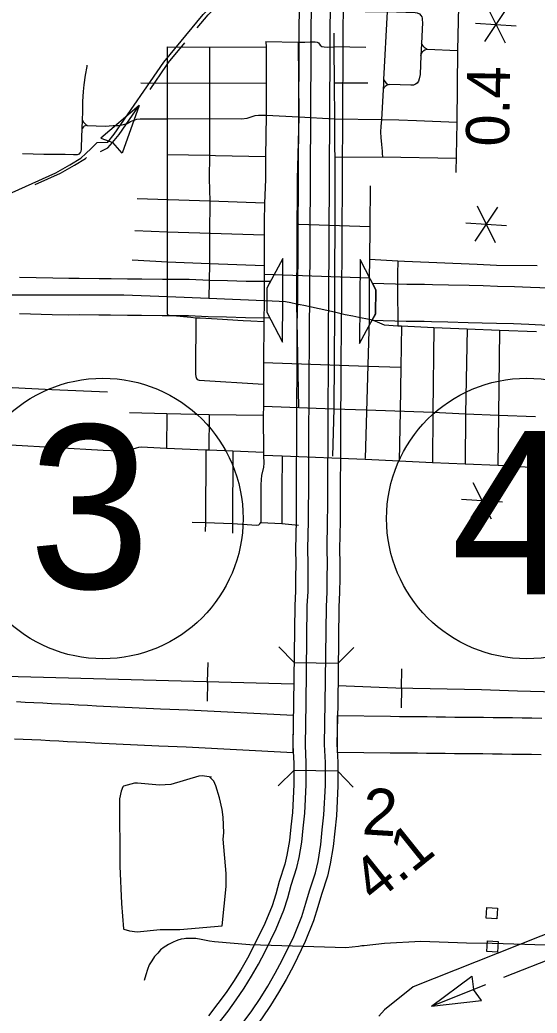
# Model space of a CAD drawing. Extents: x 1366406 to 1373462, y 376856 to 381998.
# Drawn here: x 1369320 to 1369377, y 379865.5 to 379974.8 of the extents above; entities that cross this region are included whole.
import ezdxf

# ---------------------------------------------------------------- set-up
doc = ezdxf.new("R2010")
doc.units = 0
for name, color, linetype in [('10', 7, 'Continuous'), ('19', 7, 'Continuous'), ('33', 7, 'Continuous'), ('35', 7, 'Continuous'), ('39', 7, 'Continuous'), ('40', 7, 'Continuous'), ('42', 7, 'Continuous'), ('43', 7, 'Continuous'), ('48', 7, 'Continuous'), ('56', 7, 'Continuous'), ('R_Draft', 7, 'Continuous')]:
    doc.layers.add(name, color=color, linetype=linetype)

msp = doc.modelspace()

# ---------------------------------------------------------------- linework, layer by layer
at = {"layer": '10'}
for points in [[(1369319.95, 379946.52), (1369323.62, 379946.42), (1369325.37, 379946.39), (1369326.53, 379946.41), (1369328.74, 379946.37), (1369330.03, 379946.36), (1369331.86, 379946.34), (1369333.42, 379946.34), (1369335.7, 379946.29), (1369338.64, 379946.29), (1369340.87, 379946.19), (1369342.86, 379946.15), (1369344.92, 379946.08), (1369347.02, 379946.07), (1369347.62, 379946.06), (1369347.21, 379945.29), (1369347.19, 379942.66), (1369347.53, 379942.01)], [(1369358.84, 379945.81), (1369359.2, 379945.12), (1369359.18, 379942.49), (1369358.78, 379941.76), (1369362.55, 379941.65), (1369364.54, 379941.65), (1369365.35, 379941.63), (1369367.13, 379941.59), (1369369.38, 379941.53), (1369370.91, 379941.49), (1369372.49, 379941.43), (1369374.37, 379941.4), (1369376.08, 379941.32), (1369378.2, 379941.24)], [(1369378.31, 379945.29), (1369376.25, 379945.37), (1369374.49, 379945.44), (1369372.6, 379945.47), (1369371.05, 379945.54), (1369369.49, 379945.58), (1369367.22, 379945.64), (1369365.44, 379945.68), (1369364.59, 379945.7), (1369362.61, 379945.7), (1369358.84, 379945.81)], [(1369347.53, 379942.01), (1369344.83, 379942.03), (1369342.75, 379942.1), (1369340.73, 379942.14), (1369338.55, 379942.24), (1369335.66, 379942.24), (1369333.38, 379942.29), (1369331.84, 379942.28), (1369329.98, 379942.31), (1369328.69, 379942.32), (1369326.52, 379942.36), (1369325.37, 379942.34), (1369323.54, 379942.37), (1369319.94, 379942.47)], [(1369350.11, 379894.18), (1369350.13, 379898.24), (1369338.51, 379898.82), (1369337.5, 379898.87), (1369336.5, 379898.91), (1369335.49, 379898.96), (1369328.44, 379899.29), (1369327.44, 379899.34), (1369326.45, 379899.39), (1369325.46, 379899.45), (1369324.47, 379899.5), (1369323.48, 379899.54), (1369322.5, 379899.59), (1369321.53, 379899.64), (1369320.56, 379899.69), (1369319.6, 379899.74)], [(1369354.98, 379894.18), (1369354.99, 379898.23), (1369360.83, 379898.16), (1369361.82, 379898.15), (1369362.82, 379898.14), (1369363.83, 379898.14), (1369364.85, 379898.13), (1369365.87, 379898.11), (1369366.89, 379898.1), (1369367.92, 379898.08), (1369368.96, 379898.08)], [(1369368.96, 379898.08), (1369370.01, 379898.07), (1369371.06, 379898.06), (1369372.12, 379898.04), (1369373.18, 379898.03), (1369374.25, 379898.01), (1369375.33, 379897.99), (1369376.41, 379897.99), (1369377.5, 379897.97)], [(1369319.41, 379895.69), (1369320.36, 379895.65), (1369321.32, 379895.6), (1369322.29, 379895.55), (1369323.28, 379895.5), (1369324.27, 379895.45), (1369325.25, 379895.4), (1369326.23, 379895.35), (1369327.24, 379895.3), (1369328.25, 379895.25), (1369335.3, 379894.92), (1369336.31, 379894.87), (1369337.32, 379894.82), (1369338.31, 379894.78), (1369350.11, 379894.18)], [(1369368.93, 379894.03), (1369367.89, 379894.04), (1369366.84, 379894.05), (1369365.81, 379894.06), (1369364.8, 379894.08), (1369363.8, 379894.09), (1369362.79, 379894.09), (1369361.78, 379894.1), (1369360.79, 379894.11), (1369354.98, 379894.18)], [(1369377.44, 379893.92), (1369376.37, 379893.94), (1369375.29, 379893.95), (1369374.2, 379893.96), (1369373.12, 379893.98), (1369372.06, 379893.99), (1369371, 379894.01), (1369369.97, 379894.02), (1369368.93, 379894.03)]]:
    msp.add_lwpolyline(points, dxfattribs=at)
at = {"layer": '19'}
for points in [[(1369352.16, 379985.3), (1369350.78, 379985.31), (1369350.56, 379943.93), (1369350.52, 379941.32), (1369350.52, 379939.77), (1369350.51, 379938.23), (1369350.5, 379936.7), (1369350.49, 379935.16), (1369350.48, 379933.63), (1369350.47, 379932.09), (1369350.47, 379930.55), (1369350.46, 379929.01), (1369350.45, 379927.47), (1369350.44, 379925.91), (1369350.43, 379924.35), (1369350.43, 379922.79), (1369350.42, 379921.24), (1369350.42, 379919.72), (1369350.34, 379916.54), (1369350.38, 379914.96), (1369350.37, 379913.44), (1369350.36, 379911.93), (1369350.28, 379910.36), (1369350.15, 379899.59)], [(1369351.53, 379899.58), (1369351.66, 379910.32), (1369351.74, 379911.89), (1369351.75, 379913.43), (1369351.76, 379914.98), (1369351.72, 379916.55), (1369351.79, 379919.7), (1369351.8, 379921.24), (1369351.81, 379922.79), (1369351.81, 379924.34), (1369351.82, 379925.9), (1369351.83, 379927.46), (1369351.84, 379929), (1369351.84, 379930.54), (1369351.85, 379932.08), (1369351.86, 379933.62), (1369351.87, 379935.16), (1369351.88, 379936.69), (1369351.89, 379938.23), (1369351.89, 379939.77), (1369351.9, 379941.31), (1369351.93, 379943.92), (1369352.16, 379985.3)], [(1369353.63, 379899.55), (1369353.76, 379910.25), (1369353.84, 379911.83), (1369353.85, 379913.41), (1369353.87, 379914.99), (1369353.83, 379916.55), (1369353.9, 379919.67), (1369353.91, 379921.23), (1369353.91, 379922.78), (1369353.92, 379924.33), (1369353.92, 379925.89), (1369353.94, 379927.44), (1369353.94, 379928.99), (1369353.95, 379930.53), (1369353.96, 379932.07), (1369353.96, 379933.61), (1369353.98, 379935.14), (1369353.98, 379936.68), (1369353.99, 379938.22), (1369354, 379939.76), (1369354.01, 379941.29), (1369354.04, 379943.9), (1369354.26, 379985.29)], [(1369354.26, 379985.29), (1369355.64, 379985.29), (1369355.42, 379943.88), (1369355.38, 379941.28), (1369355.38, 379939.75), (1369355.37, 379938.21), (1369355.36, 379936.67), (1369355.35, 379935.13), (1369355.34, 379933.6), (1369355.33, 379932.07), (1369355.33, 379930.53), (1369355.32, 379928.98), (1369355.31, 379927.43), (1369355.3, 379925.88), (1369355.29, 379924.33), (1369355.29, 379922.78), (1369355.28, 379921.22), (1369355.28, 379919.65), (1369355.2, 379916.55), (1369355.24, 379915), (1369355.23, 379913.4), (1369355.22, 379911.79), (1369355.14, 379910.21), (1369355.01, 379899.53)], [(1369337.9, 379860.21), (1369338.82, 379861.06), (1369339.98, 379862.15), (1369341.05, 379863.38), (1369341.85, 379864.3), (1369342.92, 379865.7), (1369343.83, 379866.95), (1369344.69, 379868.22), (1369345.51, 379869.53), (1369346.29, 379870.87), (1369347.01, 379872.25), (1369348.24, 379874.77), (1369349.07, 379876.83), (1369349.5, 379878.18), (1369349.89, 379879.56), (1369350.52, 379881.5), (1369350.77, 379882.6), (1369351.07, 379884.31), (1369351.22, 379885.86), (1369351.39, 379887.48), (1369351.54, 379890.61), (1369351.55, 379893.04), (1369351.45, 379894.98), (1369351.53, 379899.62)], [(1369350.15, 379899.59), (1369350.07, 379894.94), (1369350.18, 379893), (1369350.17, 379890.65), (1369350.02, 379887.58), (1369349.85, 379886), (1369349.7, 379884.49), (1369349.42, 379882.87), (1369349.19, 379881.87), (1369348.57, 379879.96), (1369348.18, 379878.58), (1369347.77, 379877.29), (1369346.99, 379875.33), (1369345.78, 379872.87), (1369345.08, 379871.54), (1369344.33, 379870.24), (1369343.54, 379868.97), (1369342.7, 379867.74), (1369341.81, 379866.53), (1369340.78, 379865.17)], [(1369342.87, 379860.16), (1369341.06, 379860.18), (1369342.65, 379862), (1369343.48, 379862.98), (1369344.6, 379864.44), (1369345.55, 379865.73), (1369346.46, 379867.07), (1369347.32, 379868.45), (1369348.13, 379869.86), (1369348.89, 379871.29), (1369350.17, 379873.92), (1369351.05, 379876.12), (1369351.51, 379877.57), (1369351.9, 379878.94), (1369352.55, 379880.94), (1369352.84, 379882.19), (1369353.16, 379884.03), (1369353.31, 379885.65), (1369353.49, 379887.31), (1369353.65, 379890.55), (1369353.66, 379893.09), (1369353.55, 379895.04), (1369353.64, 379899.67)], [(1369355.01, 379899.53), (1369354.93, 379895.08), (1369355.04, 379893.12), (1369355.03, 379890.52), (1369354.86, 379887.2), (1369354.68, 379885.51), (1369354.52, 379883.84), (1369354.19, 379881.92), (1369353.88, 379880.57), (1369353.22, 379878.54), (1369352.83, 379877.18), (1369352.35, 379875.65), (1369351.43, 379873.36), (1369350.12, 379870.67), (1369349.34, 379869.19), (1369348.5, 379867.74), (1369347.61, 379866.32), (1369346.67, 379864.94), (1369345.7, 379863.61), (1369344.55, 379862.11), (1369343.69, 379861.1), (1369342.87, 379860.16)]]:
    msp.add_lwpolyline(points, dxfattribs=at)
at = {"layer": '33'}
for points in [[(1369360.74, 379979.76), (1369360.6, 379977.67), (1369360.47, 379975.75), (1369360.07, 379968.28), (1369360.06, 379967.82), (1369360.03, 379967.16), (1369359.83, 379963.84)], [(1369368.35, 379978), (1369368.19, 379971.47), (1369368.16, 379967.55), (1369368.12, 379963.54), (1369368.01, 379958.02)], [(1369358.04, 379975.78), (1369360.47, 379975.75), (1369363.55, 379975.66), (1369363.76, 379975.63), (1369364.01, 379975.5), (1369364.16, 379975.32), (1369364.26, 379975.18), (1369364.32, 379975.04), (1369364.33, 379974.85), (1369364.34, 379974.54), (1369364.25, 379972.23), (1369364.18, 379970.93), (1369364.08, 379968.84), (1369364, 379968.34), (1369363.92, 379968.1), (1369363.76, 379967.87), (1369363.59, 379967.76), (1369363.37, 379967.66), (1369363.08, 379967.64), (1369360.71, 379967.73)], [(1369347.1, 379972.46), (1369347.12, 379971.85), (1369347.11, 379967.83), (1369347.11, 379964.3), (1369347.05, 379959.81), (1369347.04, 379957.27), (1369346.95, 379954.65), (1369346.91, 379952.62), (1369346.9, 379951.19), (1369346.9, 379947.75), (1369346.91, 379946.85), (1369346.9, 379943.96)], [(1369347.1, 379972.46), (1369350.64, 379972.39), (1369351.37, 379972.39), (1369351.96, 379972.42), (1369352.54, 379972.42), (1369352.74, 379972.39), (1369352.89, 379972.3), (1369353.09, 379972.04), (1369353.26, 379971.92), (1369353.53, 379971.87), (1369353.84, 379971.83), (1369354.58, 379971.86)], [(1369350.64, 379972.41), (1369350.64, 379972.39), (1369350.71, 379964.12), (1369350.54, 379957.32), (1369350.46, 379943.59), (1369350.69, 379932.15)], [(1369354.57, 379973.39), (1369354.58, 379971.86), (1369354.62, 379967.87), (1369354.65, 379963.92), (1369354.7, 379956.6), (1369354.65, 379942.7), (1369354.59, 379932.03), (1369354.42, 379926.8)], [(1369346.88, 379941.58), (1369345.45, 379941.65), (1369344.59, 379941.7), (1369341.74, 379941.89), (1369341.11, 379941.93), (1369339.85, 379941.99), (1369339.38, 379942), (1369338.81, 379942.07), (1369336.44, 379942.3), (1369336.29, 379942.38), (1369336.26, 379942.43), (1369336.25, 379944.38), (1369336.25, 379948.18), (1369336.26, 379951.51), (1369336.26, 379960.03), (1369336.27, 379963.93), (1369336.27, 379971.86)], [(1369336.27, 379971.86), (1369347.12, 379971.85)], [(1369340.87, 379971.85), (1369340.87, 379959.94), (1369340.86, 379957.37), (1369340.9, 379954.88), (1369340.87, 379951.37), (1369340.87, 379947.97), (1369340.82, 379944.19)], [(1369358.11, 379971.79), (1369354.58, 379971.86)], [(1369364.18, 379970.93), (1369364.27, 379971.21), (1369364.39, 379971.37), (1369364.5, 379971.46), (1369364.62, 379971.55), (1369364.85, 379971.61), (1369364.76, 379971.66), (1369364.63, 379971.72), (1369364.49, 379971.86), (1369364.37, 379972.02), (1369364.25, 379972.23)], [(1369364.85, 379971.61), (1369368.19, 379971.47)], [(1369326.77, 379960.87), (1369326.85, 379962.89), (1369326.87, 379963.79), (1369326.92, 379964.74), (1369326.92, 379965.84), (1369327, 379966.95), (1369327.07, 379967.68), (1369327.22, 379968.74), (1369327.39, 379969.72), (1369327.41, 379969.84)], [(1369360.07, 379968.28), (1369360.21, 379968.06), (1369360.36, 379967.87), (1369360.48, 379967.77), (1369360.71, 379967.73), (1369360.47, 379967.67), (1369360.25, 379967.5), (1369360.1, 379967.35), (1369360.03, 379967.16)], [(1369347.11, 379967.83), (1369333.3, 379967.88)], [(1369358.31, 379967.89), (1369354.62, 379967.87)], [(1369326.87, 379963.79), (1369326.97, 379963.63), (1369327.05, 379963.53), (1369327.09, 379963.47), (1369327.25, 379963.32), (1369327.39, 379963.22), (1369327.23, 379963.19), (1369327.08, 379963.14), (1369326.99, 379963.07), (1369326.85, 379962.89)], [(1369327.39, 379963.22), (1369329.39, 379963.13), (1369330.28, 379963.21), (1369330.79, 379963.22), (1369331.25, 379963.3), (1369331.8, 379963.44), (1369332.18, 379963.65), (1369332.53, 379963.78), (1369332.86, 379963.9), (1369333.24, 379963.94), (1369336.27, 379963.93)], [(1369368.12, 379963.54), (1369363.7, 379963.72), (1369361.75, 379963.79), (1369359.83, 379963.84), (1369354.65, 379963.92), (1369350.71, 379964.12), (1369347.11, 379964.3), (1369346.63, 379964.33), (1369346.28, 379964.33), (1369345.89, 379964.28), (1369345.01, 379964), (1369344.44, 379963.91), (1369336.27, 379963.93)], [(1369359.83, 379963.84), (1369359.77, 379963.12), (1369359.73, 379962.49), (1369359.75, 379961.89), (1369359.82, 379961.12), (1369359.89, 379960.39), (1369359.92, 379960.12), (1369359.96, 379959.76)], [(1369320.26, 379960.13), (1369322.64, 379960.06), (1369324.96, 379960.06), (1369325.89, 379960.01), (1369326.18, 379960), (1369326.34, 379960.03), (1369326.54, 379960.1), (1369326.66, 379960.23), (1369326.74, 379960.39), (1369326.76, 379960.56), (1369326.77, 379960.87)], [(1369336.26, 379960.03), (1369340.87, 379959.94), (1369341.55, 379959.92), (1369347.05, 379959.81)], [(1369354.65, 379959.71), (1369359.96, 379959.76), (1369368.06, 379959.63)], [(1369358.59, 379956.56), (1369358.53, 379952.1), (1369358.51, 379948.44), (1369358.47, 379946.44), (1369358.48, 379941.87), (1369358.32, 379936.83), (1369358.04, 379926.56)], [(1369346.95, 379954.65), (1369340.9, 379954.88), (1369332.92, 379955.12)], [(1369332.65, 379951.64), (1369336.26, 379951.51), (1369346.9, 379951.19), (1369346.9, 379951.19)], [(1369350.74, 379952.34), (1369358.53, 379952.1)], [(1369340.87, 379947.97), (1369336.25, 379948.18), (1369332.35, 379948.37)], [(1369376.97, 379947.76), (1369372.5, 379947.79), (1369370.39, 379947.89), (1369362.35, 379948.25), (1369361.64, 379948.27), (1369358.51, 379948.44)], [(1369346.9, 379947.75), (1369340.87, 379947.97)], [(1369361.64, 379948.27), (1369361.6, 379946.87), (1369361.6, 379945.42), (1369361.65, 379941.17)], [(1369346.91, 379946.85), (1369358.47, 379946.44)], [(1369318.15, 379944.55), (1369321.4, 379944.57), (1369331.45, 379944.57), (1369336.25, 379944.38), (1369340.82, 379944.19), (1369346.9, 379943.96), (1369347.8, 379943.92), (1369348.57, 379943.88), (1369349.25, 379943.82), (1369349.84, 379943.73), (1369350.46, 379943.59), (1369351.27, 379943.43), (1369354.65, 379942.7), (1369355.84, 379942.41), (1369356.67, 379942.24), (1369357.34, 379942.11), (1369358.48, 379941.87), (1369358.83, 379941.81), (1369359, 379941.74), (1369359.34, 379941.61), (1369359.86, 379941.36), (1369360.11, 379941.25), (1369361.65, 379941.17), (1369362.05, 379941.14), (1369365.61, 379940.97), (1369369.26, 379940.81), (1369372.83, 379940.68), (1369376.9, 379940.52)], [(1369346.9, 379943.96), (1369346.88, 379941.58), (1369346.84, 379937.13), (1369346.83, 379934.73), (1369346.82, 379932.29), (1369346.81, 379931.29), (1369346.82, 379927.22)], [(1369339.38, 379942), (1369339.34, 379936.3), (1369339.34, 379935.84), (1369339.38, 379935.56), (1369339.45, 379935.37), (1369339.53, 379935.23), (1369339.73, 379935.16), (1369346.83, 379934.73)], [(1369362.05, 379941.14), (1369361.97, 379936.59), (1369361.9, 379931.79), (1369361.77, 379926.24)], [(1369365.61, 379940.97), (1369365.49, 379931.63), (1369365.45, 379926.08)], [(1369369.26, 379940.81), (1369369.08, 379931.46), (1369369.07, 379925.93)], [(1369372.83, 379940.68), (1369372.71, 379931.31), (1369372.67, 379925.77)], [(1369346.84, 379937.13), (1369358.32, 379936.71), (1369361.97, 379936.59)], [(1369316.88, 379934.48), (1369323.49, 379934.16), (1369329.63, 379933.88)], [(1369346.82, 379932.29), (1369354.59, 379932.03), (1369358.19, 379931.91), (1369365.49, 379931.63), (1369369.08, 379931.46), (1369372.71, 379931.31), (1369376.8, 379931.16)], [(1369346.81, 379931.29), (1369340.83, 379931.37), (1369336.19, 379931.47), (1369332.08, 379931.57)], [(1369336.19, 379931.47), (1369336.13, 379927.66)], [(1369340.83, 379931.37), (1369340.8, 379927.48)], [(1369331.92, 379927.37), (1369331.33, 379927.31), (1369330.81, 379927.37), (1369329.16, 379927.43), (1369318.95, 379928.03)], [(1369346.82, 379927.22), (1369343.47, 379927.37), (1369340.8, 379927.48), (1369340.48, 379927.47), (1369336.13, 379927.66), (1369333.35, 379927.8), (1369333.06, 379927.77), (1369332.79, 379927.7), (1369332.42, 379927.58), (1369331.92, 379927.37)], [(1369340.48, 379927.47), (1369340.43, 379919.49), (1369340.42, 379918.49)], [(1369343.47, 379927.37), (1369343.43, 379919.37), (1369343.43, 379918.33)], [(1369346.82, 379927.22), (1369346.83, 379926.89), (1369346.86, 379926.04), (1369346.82, 379925.6), (1369346.62, 379924.68), (1369346.57, 379924.22), (1369346.54, 379923.65), (1369346.52, 379919.5)], [(1369376.86, 379925.52), (1369372.69, 379925.77), (1369369.07, 379925.93), (1369365.45, 379926.08), (1369361.77, 379926.24), (1369358.05, 379926.44), (1369348.9, 379926.82), (1369346.83, 379926.89)], [(1369348.9, 379926.82), (1369348.84, 379923.05), (1369348.84, 379919.38)], [(1369338.98, 379919.53), (1369340.43, 379919.49), (1369343.43, 379919.37), (1369346.09, 379919.2), (1369346.31, 379919.24), (1369346.44, 379919.35), (1369346.52, 379919.5)], [(1369346.52, 379919.5), (1369348.84, 379919.38), (1369350.67, 379919.21)]]:
    msp.add_lwpolyline(points, dxfattribs=at)
at = {"layer": '35'}
msp.add_lwpolyline([(1369341.11, 379891.47), (1369340.07, 379891.59), (1369339.7, 379891.57), (1369336.61, 379890.64), (1369335.37, 379890.59), (1369332.94, 379890.81), (1369332.62, 379890.8), (1369331.41, 379890.46), (1369331.35, 379890.41), (1369331.14, 379889.91), (1369330.96, 379889.06), (1369331.01, 379881.65), (1369331.17, 379877.56), (1369331.39, 379874.76), (1369331.39, 379874.76), (1369331.45, 379874.72), (1369332.08, 379874.54), (1369332.91, 379874.43), (1369335.43, 379874.68), (1369337.62, 379874.68), (1369342.29, 379875.08), (1369342.72, 379879.41), (1369342.7, 379880.84), (1369342.38, 379884.62), (1369342.45, 379885.32), (1369342.39, 379887.05), (1369342.28, 379887.88), (1369341.99, 379889.18), (1369341.59, 379890.49), (1369341.37, 379891), (1369340.89, 379891.51), (1369340.95, 379891.5)], dxfattribs=at)
at = {"layer": '39'}
for p, q in [((1369350.21, 379904.08), (1369348.51, 379905.82)), ((1369355.07, 379904.02), (1369356.8, 379905.72)), ((1369350.21, 379904.08), (1369355.07, 379904.02)), ((1369350.17, 379892.19), (1369348.43, 379890.5)), ((1369355.03, 379892.11), (1369350.17, 379892.19)), ((1369355.03, 379892.11), (1369356.72, 379890.37))]:
    msp.add_line(p, q, dxfattribs=at)
at = {"layer": '40'}
for p, q in [((1369340.66, 379901.95), (1369340.72, 379904.09)), ((1369362.04, 379901.24), (1369362.08, 379903.38)), ((1369340.66, 379901.95), (1369340.61, 379899.81)), ((1369362.04, 379901.24), (1369361.99, 379899.11))]:
    msp.add_line(p, q, dxfattribs=at)
for points in [[(1369350.18, 379901.69), (1369311.51, 379902.74), (1369293.42, 379903.21), (1369277.92, 379903.72), (1369268.52, 379903.93), (1369263.7, 379904.07), (1369258.5, 379904.23), (1369254.42, 379904.3), (1369247.2, 379904.6), (1369241.4, 379904.25), (1369238.18, 379903.9), (1369237.81, 379903.86), (1369237.29, 379903.77), (1369235.28, 379903.59), (1369220.06, 379904.06), (1369214.47, 379904.51), (1369213.67, 379904.64), (1369212.34, 379904.91), (1369211.48, 379905.04), (1369210.58, 379905.07), (1369210.16, 379905.04), (1369209.93, 379905.05), (1369209.63, 379905.01), (1369209.17, 379904.93)], [(1369379.12, 379900.81), (1369374.81, 379900.92), (1369370.87, 379901.06), (1369361.43, 379901.26), (1369355.04, 379901.5)], [(1369378.98, 379872.92), (1369375.64, 379873.02), (1369372.02, 379873.13), (1369369.19, 379873.18), (1369364.18, 379873.38), (1369360.15, 379873.14), (1369357.92, 379872.9), (1369357.66, 379872.87), (1369357.29, 379872.81), (1369355.9, 379872.68), (1369345.33, 379873.01), (1369341.45, 379873.32), (1369340.89, 379873.41), (1369339.97, 379873.6), (1369339.37, 379873.69), (1369338.74, 379873.71), (1369338.45, 379873.69), (1369338.29, 379873.7), (1369338.09, 379873.67), (1369337.77, 379873.62), (1369337.38, 379873.51), (1369337.12, 379873.41), (1369336.94, 379873.33), (1369336.64, 379873.18), (1369336.37, 379873.02), (1369336.08, 379872.85), (1369335.88, 379872.74), (1369335.5, 379872.44), (1369335.17, 379872.07), (1369334.83, 379871.71), (1369334.52, 379871.25), (1369334.23, 379870.78), (1369334.04, 379870.28), (1369333.85, 379869.69), (1369333.67, 379869.07)]]:
    msp.add_lwpolyline(points, dxfattribs=at)
at = {"layer": '42'}
for p, q in [((1369348.98, 379948.58), (1369347.21, 379945.29)), ((1369348.95, 379943.96), (1369348.98, 379948.58)), ((1369357.48, 379948.44), (1369357.44, 379943.82)), ((1369359.2, 379945.12), (1369357.48, 379948.44)), ((1369347.21, 379945.29), (1369347.19, 379942.66)), ((1369359.18, 379942.49), (1369359.2, 379945.12)), ((1369348.91, 379939.34), (1369348.95, 379943.96)), ((1369357.44, 379943.82), (1369357.41, 379939.2)), ((1369347.19, 379942.66), (1369348.91, 379939.34)), ((1369357.41, 379939.2), (1369359.18, 379942.49))]:
    msp.add_line(p, q, dxfattribs=at)
at = {"layer": '43'}
for p, q in [((1369333.12, 379965.42), (1369328.89, 379961.81)), ((1369333.12, 379965.42), (1369331.26, 379960.18)), ((1369328.89, 379961.81), (1369330.23, 379961.35)), ((1369331.26, 379960.18), (1369330.23, 379961.33)), ((1369365.33, 379866.24), (1369369.79, 379869.55)), ((1369369.79, 379869.55), (1369369.96, 379868.08)), ((1369370.85, 379866.88), (1369369.97, 379868.06)), ((1369365.33, 379866.24), (1369370.85, 379866.88))]:
    msp.add_line(p, q, dxfattribs=at)
for points in [[(1369335.86, 379970.19), (1369340.2, 379975.43), (1369342.65, 379977.96), (1369343.17, 379978.76), (1369343.85, 379979.75), (1369344.55, 379980.73), (1369345.78, 379982.02), (1369346.51, 379983.1), (1369347.28, 379983.91), (1369347.88, 379984.65), (1369348.65, 379985.8), (1369348.99, 379986.59), (1369349.31, 379987.28), (1369355.51, 379993.24), (1369356.07, 379994.05)], [(1369339.53, 379973.96), (1369340.72, 379975.4), (1369343.17, 379977.92), (1369343.69, 379978.73), (1369343.73, 379978.79)], [(1369336.15, 379969.82), (1369336.38, 379970.16), (1369338.17, 379972.32)], [(1369240.75, 379946.04), (1369268.24, 379945.31), (1369274.5, 379945.21), (1369278.25, 379945.43), (1369284.48, 379946), (1369287.13, 379946.46), (1369299.97, 379948.83), (1369306.31, 379949.86), (1369307.96, 379950.28), (1369308.5, 379950.58), (1369309.76, 379951.17), (1369313.65, 379953.1), (1369317.24, 379954.99), (1369323.94, 379958.01), (1369325.5, 379958.87), (1369326.69, 379959.63), (1369327.27, 379960.12), (1369327.85, 379960.68), (1369328.49, 379961.35), (1369329.68, 379961.38), (1369330.39, 379962.24), (1369335.86, 379970.19)], [(1369334.33, 379967.18), (1369336.15, 379969.82)], [(1369328.88, 379960.34), (1369329.69, 379960.76), (1369330.2, 379961.34), (1369330.91, 379962.21), (1369333.12, 379965.42)], [(1369321.66, 379956.71), (1369324.46, 379957.98), (1369326.02, 379958.83), (1369327.21, 379959.59), (1369327.32, 379959.69)], [(1369434.66, 379901.35), (1369434.19, 379900.9), (1369434.01, 379900.32), (1369433.78, 379899.84), (1369433.16, 379899.07), (1369432.61, 379898.31), (1369431.98, 379898.05), (1369431.44, 379897.75), (1369430.46, 379897.03), (1369429.65, 379896.27), (1369428.9, 379895.42), (1369428.12, 379894.47), (1369427.7, 379894.1), (1369427.17, 379893.65), (1369425.93, 379893.07), (1369422.93, 379891.84), (1369407.66, 379885.94), (1369363.34, 379868.38), (1369360.15, 379865.84), (1369359.55, 379865.13)], [(1369379.25, 379871.75), (1369373.28, 379869.39)], [(1369371.29, 379868.6), (1369366.03, 379866.51), (1369365.34, 379866.24)]]:
    msp.add_lwpolyline(points, dxfattribs=at)
at = {"layer": '48'}
for p, q in [((1369373.69, 379976.21), (1369371.2, 379972.46)), ((1369371.45, 379976.35), (1369373.45, 379972.32)), ((1369370.2, 379974.48), (1369374.69, 379974.19)), ((1369372.61, 379954.22), (1369370.12, 379950.47)), ((1369370.36, 379954.36), (1369372.36, 379950.33)), ((1369369.12, 379952.49), (1369373.61, 379952.21)), ((1369372.15, 379923.78), (1369369.66, 379920.03)), ((1369369.9, 379923.92), (1369371.9, 379919.89)), ((1369368.66, 379922.05), (1369373.15, 379921.77))]:
    msp.add_line(p, q, dxfattribs=at)
at = {"layer": '56'}
for points in [[(1369371.36, 379875.93), (1369371.44, 379877.1), (1369372.61, 379877.03), (1369372.54, 379875.86)], [(1369371.44, 379872.26), (1369371.52, 379873.43), (1369372.69, 379873.36), (1369372.62, 379872.19)]]:
    msp.add_lwpolyline(points, close=True, dxfattribs=at)
at = {"layer": 'R_Draft'}
for centre in [(1369329.14, 379919.94), (1369375.84, 379919.94)]:
    msp.add_circle(centre, 15.45, dxfattribs=at)

# ---------------------------------------------------------------- texts
at = {"layer": '39'}
msp.add_text('2', height=5.13, rotation=356.4139, dxfattribs=at).set_placement((1369357.61, 379885.18))
at = {"layer": '48'}
for s, rotation, p in [('0.4', 89.0752, (1369373.87, 379960.86)), ('4.1', 38.7312, (1369359.08, 379877.51))]:
    msp.add_text(s, height=4.752, rotation=rotation, dxfattribs=at).set_placement(p)
at = {"layer": 'R_Draft'}
for s, p in [('3', (1369320.95, 379912.24)), ('4', (1369367.5, 379911.59))]:
    msp.add_text(s, height=18, dxfattribs=at).set_placement(p)

doc.saveas('drawing.dxf')
